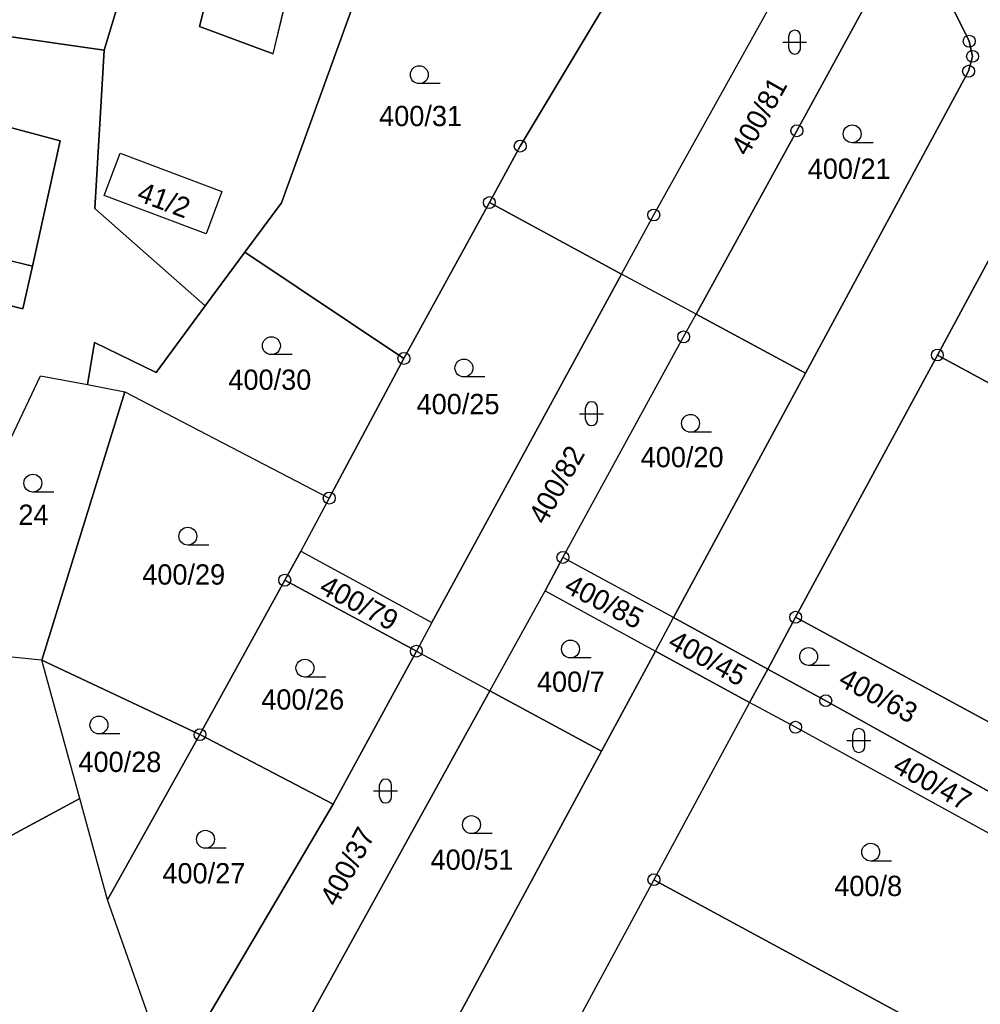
# Model space of a CAD drawing. Extents: x -654083 to -650132, y -1099819 to -1096699.
# Drawn here: x -652350.7 to -652270.1, y -1098133.4 to -1098050.9 of the extents above; entities that cross this region are included whole.
import ezdxf

# ---------------------------------------------------------------- set-up
doc = ezdxf.new("R2010")
doc.units = 0
for name, color, linetype in [('Geodetické body', 7, 'Continuous'), ('Hranice - vnitř_ kresba', 7, 'Continuous'), ('Obvody jako plochy', 7, 'Continuous'), ('Parcelní čísla', 7, 'Continuous'), ('Značky kultur', 7, 'Continuous')]:
    doc.layers.add(name, color=color, linetype=linetype)

msp = doc.modelspace()

# ---------------------------------------------------------------- linework, layer by layer
at = {"layer": 'Geodetické body'}
for centre, radius in [((-652271.05, -1098052.68), 0.5), ((-652271.05, -1098052.68), 0.001), ((-652270.77, -1098053.95), 0.5), ((-652270.77, -1098053.95), 0.001), ((-652271.1, -1098055.2), 0.5), ((-652271.1, -1098055.2), 0.001), ((-652285.49, -1098060.19), 0.5), ((-652285.49, -1098060.19), 0.001), ((-652308.69, -1098061.47), 0.5), ((-652308.69, -1098061.47), 0.001), ((-652311.28, -1098066.21), 0.5), ((-652311.28, -1098066.21), 0.001), ((-652297.49, -1098067.25), 0.5), ((-652297.49, -1098067.25), 0.001), ((-652294.99, -1098077.47), 0.5), ((-652294.99, -1098077.47), 0.001), ((-652318.44, -1098079.28), 0.5), ((-652273.72, -1098078.99), 0.5), ((-652273.72, -1098078.99), 0.001), ((-652318.44, -1098079.28), 0.001), ((-652324.7, -1098090.99), 0.5), ((-652324.7, -1098090.99), 0.001), ((-652305.11, -1098095.96), 0.5), ((-652305.11, -1098095.96), 0.001), ((-652328.43, -1098097.87), 0.5), ((-652328.43, -1098097.87), 0.001), ((-652285.6, -1098100.98), 0.5), ((-652285.6, -1098100.98), 0.001), ((-652317.4, -1098103.82), 0.5), ((-652317.4, -1098103.82), 0.001), ((-652283.08, -1098107.97), 0.5), ((-652283.08, -1098107.97), 0.001), ((-652285.61, -1098110.2), 0.5), ((-652335.54, -1098110.82), 0.5), ((-652285.61, -1098110.2), 0.001), ((-652335.54, -1098110.82), 0.001), ((-652297.48, -1098122.98), 0.5), ((-652297.48, -1098122.98), 0.001)]:
    msp.add_circle(centre, radius, dxfattribs=at)
at = {"layer": 'Hranice - vnitř_ kresba'}
for p, q in [((-652329.39, -1098053.75), (-652325.09, -1098035.62)), ((-652335.57, -1098051.46), (-652333.97, -1098044.99)), ((-652329.39, -1098053.75), (-652335.57, -1098051.46)), ((-652356.45, -1098069.89), (-652349.59, -1098071.53))]:
    msp.add_line(p, q, dxfattribs=at)
at = {"layer": 'Obvody jako plochy'}
for points in [[(-652283.6, -1098024.55), (-652287.57, -1098022.38), (-652299.65, -1098046.36), (-652308.69, -1098061.47), (-652311.28, -1098066.21), (-652300.19, -1098072.2), (-652297.49, -1098067.25), (-652279.65, -1098035.21), (-652276.24, -1098028.56)], [(-652260.84, -1098055.14), (-652273.72, -1098078.99), (-652285.6, -1098100.98), (-652287.94, -1098105.32), (-652295.85, -1098101.01), (-652284.78, -1098080.52), (-652271.1, -1098055.2), (-652270.77, -1098053.95), (-652271.05, -1098052.68), (-652275.93, -1098042.78), (-652266.76, -1098026.38), (-652268.48, -1098031.66), (-652253.8, -1098039.57)], [(-652318.27, -1098037.45), (-652320.62, -1098036.82), (-652332.1, -1098029.44), (-652333.63, -1098033.34), (-652335.08, -1098032.88), (-652338.27, -1098031.87), (-652341.44, -1098046.38), (-652343.57, -1098053.42), (-652344.35, -1098066.72), (-652335.1, -1098074.87), (-652331.77, -1098070.37), (-652328.7, -1098066.22)], [(-652329.39, -1098053.75), (-652325.09, -1098035.62), (-652333.63, -1098033.34), (-652336.58, -1098044.22), (-652333.97, -1098044.99), (-652335.57, -1098051.46)], [(-652299.65, -1098046.36), (-652319.73, -1098034.98), (-652320.62, -1098036.82), (-652318.27, -1098037.45), (-652328.7, -1098066.22), (-652331.77, -1098070.37), (-652318.44, -1098079.28), (-652311.28, -1098066.21), (-652308.69, -1098061.47)], [(-652275.93, -1098042.78), (-652278.28, -1098046.99), (-652285.49, -1098060.19), (-652293.94, -1098075.57), (-652300.19, -1098072.2), (-652297.49, -1098067.25), (-652279.65, -1098035.21)], [(-652271.1, -1098055.2), (-652284.78, -1098080.52), (-652293.94, -1098075.57), (-652285.49, -1098060.19), (-652278.28, -1098046.99), (-652275.93, -1098042.78), (-652271.05, -1098052.68), (-652270.77, -1098053.95)], [(-652348.9, -1098080.73), (-652344.98, -1098081.47), (-652344.39, -1098077.93), (-652339.22, -1098080.46), (-652335.1, -1098074.87), (-652344.35, -1098066.72), (-652343.57, -1098053.42), (-652360.95, -1098050.95), (-652364.91, -1098059.51), (-652358.22, -1098061.13), (-652357.52, -1098058.3), (-652347.27, -1098061.03), (-652349.59, -1098071.53), (-652350.38, -1098075.11), (-652357.25, -1098073.39), (-652360.8, -1098072.57), (-652375.17, -1098080.77), (-652351.38, -1098085.94)], [(-652255.63, -1098057.57), (-652241.86, -1098065.29), (-652239.31, -1098067.73), (-652234.55, -1098070.66), (-652243.62, -1098089.21), (-652246.14, -1098093.94), (-652273.72, -1098078.99), (-652260.84, -1098055.14)], [(-652349.59, -1098071.53), (-652347.27, -1098061.03), (-652357.52, -1098058.3), (-652358.22, -1098061.13), (-652364.91, -1098059.51), (-652367.09, -1098067.32), (-652375.17, -1098080.77), (-652360.8, -1098072.57), (-652357.25, -1098073.39), (-652350.38, -1098075.11)], [(-652364.91, -1098059.51), (-652358.22, -1098061.13), (-652357.52, -1098058.3), (-652347.27, -1098061.03), (-652349.59, -1098071.53), (-652356.45, -1098069.89), (-652357.25, -1098073.39), (-652360.8, -1098072.57), (-652359.97, -1098069.04), (-652367.09, -1098067.32)], [(-652343.56, -1098065.62), (-652342.24, -1098062.08), (-652333.7, -1098065.28), (-652335.02, -1098068.82)], [(-652333.7, -1098065.28), (-652335.02, -1098068.82), (-652343.56, -1098065.62), (-652342.24, -1098062.08)], [(-652333.7, -1098065.28), (-652335.02, -1098068.82), (-652343.56, -1098065.62), (-652342.24, -1098062.08)], [(-652300.19, -1098072.2), (-652311.28, -1098066.21), (-652318.44, -1098079.28), (-652324.7, -1098090.99), (-652327.08, -1098095.44), (-652316.1, -1098101.42)], [(-652324.7, -1098090.99), (-652318.44, -1098079.28), (-652331.77, -1098070.37), (-652335.1, -1098074.87), (-652339.22, -1098080.46), (-652344.39, -1098077.93), (-652344.98, -1098081.47), (-652341.84, -1098082.08)], [(-652311.23, -1098107.15), (-652306.6, -1098098.77), (-652305.11, -1098095.96), (-652294.99, -1098077.47), (-652293.94, -1098075.57), (-652300.19, -1098072.2), (-652316.1, -1098101.42), (-652317.4, -1098103.82)], [(-652284.78, -1098080.52), (-652295.85, -1098101.01), (-652305.11, -1098095.96), (-652294.99, -1098077.47), (-652293.94, -1098075.57)], [(-652273.72, -1098078.99), (-652246.14, -1098093.94), (-652251.67, -1098104.34), (-652257.9, -1098116.01), (-652285.6, -1098100.98)], [(-652341.84, -1098082.08), (-652348.8, -1098104.58), (-652367.35, -1098102.73), (-652366.91, -1098097.18), (-652363.31, -1098098.3), (-652362.49, -1098095.54), (-652355.47, -1098097.67), (-652353.47, -1098090.56), (-652372.41, -1098084.66), (-652374.63, -1098091.76), (-652376.21, -1098096.84), (-652379.95, -1098094.79), (-652375.17, -1098080.77), (-652351.38, -1098085.94), (-652348.9, -1098080.73), (-652344.98, -1098081.47)], [(-652327.08, -1098095.44), (-652328.43, -1098097.87), (-652335.54, -1098110.82), (-652348.8, -1098104.58), (-652341.84, -1098082.08), (-652324.7, -1098090.99)], [(-652316.1, -1098101.42), (-652317.4, -1098103.82), (-652328.43, -1098097.87), (-652327.08, -1098095.44)], [(-652295.85, -1098101.01), (-652305.11, -1098095.96), (-652306.6, -1098098.77), (-652297.36, -1098103.81)], [(-652317.4, -1098103.82), (-652324.37, -1098116.66), (-652335.54, -1098110.82), (-652328.43, -1098097.87)], [(-652306.6, -1098098.77), (-652297.36, -1098103.81), (-652301.89, -1098112.2), (-652311.23, -1098107.15)], [(-652287.94, -1098105.32), (-652289.46, -1098108.13), (-652297.36, -1098103.81), (-652295.85, -1098101.01)], [(-652285.6, -1098100.98), (-652257.9, -1098116.01), (-652260.36, -1098120.62), (-652283.08, -1098107.97), (-652287.94, -1098105.32)], [(-652348.8, -1098104.58), (-652367.35, -1098102.73), (-652376.94, -1098102.1), (-652375.09, -1098108.69), (-652379.86, -1098116.48), (-652371.41, -1098121.18), (-652362.11, -1098126.39), (-652357.82, -1098117.99), (-652353.4, -1098120.37), (-652345.62, -1098116.16)], [(-652311.23, -1098107.15), (-652326.55, -1098134.91), (-652330.03, -1098136.21), (-652333.75, -1098138.69), (-652336.77, -1098143.18), (-652337.98, -1098139.73), (-652324.37, -1098116.66), (-652317.4, -1098103.82)], [(-652289.46, -1098108.13), (-652297.48, -1098122.98), (-652308.89, -1098144.1), (-652276.57, -1098161.63), (-652277.81, -1098164.27), (-652287.06, -1098159.19), (-652306.84, -1098148.4), (-652327.75, -1098137.08), (-652326.55, -1098134.91), (-652326.07, -1098134.73), (-652313.79, -1098134.25), (-652301.89, -1098112.2), (-652297.36, -1098103.81)], [(-652335.54, -1098110.82), (-652343.28, -1098124.66), (-652345.62, -1098116.16), (-652348.8, -1098104.58)], [(-652257.7, -1098121.96), (-652257.51, -1098122.07), (-652258.96, -1098124.77), (-652265.36, -1098121.32), (-652285.61, -1098110.2), (-652289.46, -1098108.13), (-652287.94, -1098105.32), (-652283.08, -1098107.97), (-652260.36, -1098120.62)], [(-652311.23, -1098107.15), (-652301.89, -1098112.2), (-652313.79, -1098134.25), (-652326.07, -1098134.73), (-652326.55, -1098134.91)], [(-652266.33, -1098139.88), (-652261.08, -1098128.71), (-652258.96, -1098124.77), (-652265.36, -1098121.32), (-652285.61, -1098110.2), (-652289.46, -1098108.13), (-652297.48, -1098122.98)], [(-652324.37, -1098116.66), (-652337.98, -1098139.73), (-652343.28, -1098124.66), (-652335.54, -1098110.82)], [(-652343.28, -1098124.66), (-652345.62, -1098116.16), (-652353.4, -1098120.37), (-652357.82, -1098117.99), (-652362.11, -1098126.39), (-652371.41, -1098121.18), (-652370.69, -1098134.78), (-652355.32, -1098140.03), (-652347.23, -1098147.65), (-652342.01, -1098148.1), (-652336.77, -1098143.18), (-652337.98, -1098139.73)], [(-652266.33, -1098139.88), (-652297.48, -1098122.98), (-652308.89, -1098144.1), (-652276.57, -1098161.63), (-652268.44, -1098144.36)]]:
    msp.add_lwpolyline(points, close=True, dxfattribs=at)
msp.add_lwpolyline([(-652360.95, -1098050.95), (-652343.57, -1098053.42), (-652341.44, -1098046.38)], dxfattribs=at)
at = {"layer": 'Značky kultur'}
for p, q in [((-652286.68, -1098052.76), (-652284.68, -1098052.76)), ((-652286.18, -1098053.26), (-652286.18, -1098052.26)), ((-652285.18, -1098053.26), (-652285.18, -1098052.26)), ((-652315.4, -1098056.24), (-652317.15, -1098056.24)), ((-652279.11, -1098061.2), (-652280.86, -1098061.2)), ((-652327.8, -1098078.96), (-652329.55, -1098078.96)), ((-652311.66, -1098080.83), (-652313.41, -1098080.83)), ((-652303.71, -1098083.91), (-652301.71, -1098083.91)), ((-652303.21, -1098084.41), (-652303.21, -1098083.41)), ((-652302.21, -1098084.41), (-652302.21, -1098083.41)), ((-652292.66, -1098085.47), (-652294.41, -1098085.47)), ((-652347.8, -1098090.48), (-652349.55, -1098090.48)), ((-652334.81, -1098094.93), (-652336.56, -1098094.93)), ((-652302.73, -1098104.39), (-652304.48, -1098104.39)), ((-652282.76, -1098105.02), (-652284.51, -1098105.02)), ((-652324.99, -1098105.99), (-652326.74, -1098105.99)), ((-652342.26, -1098110.76), (-652344.01, -1098110.76)), ((-652281.3, -1098111.31), (-652279.3, -1098111.31)), ((-652280.8, -1098111.81), (-652280.8, -1098110.81)), ((-652279.8, -1098111.81), (-652279.8, -1098110.81)), ((-652320.98, -1098115.54), (-652318.98, -1098115.54)), ((-652320.48, -1098116.04), (-652320.48, -1098115.04)), ((-652319.48, -1098116.04), (-652319.48, -1098115.04)), ((-652311.03, -1098119.11), (-652312.78, -1098119.11)), ((-652333.33, -1098120.34), (-652335.08, -1098120.34)), ((-652277.56, -1098121.42), (-652279.31, -1098121.42))]:
    msp.add_line(p, q, dxfattribs=at)
for centre in [(-652317.15, -1098055.49), (-652280.86, -1098060.45), (-652329.55, -1098078.21), (-652313.41, -1098080.08), (-652294.41, -1098084.72), (-652349.55, -1098089.73), (-652336.56, -1098094.18), (-652304.48, -1098103.64), (-652284.51, -1098104.27), (-652326.74, -1098105.24), (-652344.01, -1098110.01), (-652312.78, -1098118.36), (-652335.08, -1098119.59), (-652279.31, -1098120.67)]:
    msp.add_circle(centre, 0.75, dxfattribs=at)
for centre, start, end in [((-652285.68, -1098052.26), 0, 180), ((-652285.68, -1098053.26), 180, 0), ((-652302.71, -1098083.41), 0, 180), ((-652302.71, -1098084.41), 180, 0), ((-652280.3, -1098110.81), 0, 180), ((-652280.3, -1098111.81), 180, 0), ((-652319.98, -1098115.04), 0, 180), ((-652319.98, -1098116.04), 180, 0)]:
    msp.add_arc(centre, 0.5, start, end, dxfattribs=at)

# ---------------------------------------------------------------- texts
at = {"layer": 'Parcelní čísla'}
for s, rotation, p in [('400/81', 60.651, (-652289.647, -1098062.405)), ('41/2', 339.624, (-652340.92, -1098066.02)), ('400/82', 60.795, (-652306.601, -1098093.304)), ('400/79', 331.722, (-652325.654, -1098098.871)), ('400/85', 332.46, (-652305.115, -1098098.806)), ('400/45', 331.191, (-652296.42, -1098103.47)), ('400/63', 331.731, (-652282.13, -1098106.63)), ('400/47', 330.822, (-652277.57, -1098113.87)), ('400/37', 61.848, (-652324.078, -1098125.325))]:
    msp.add_text(s, height=1.7, rotation=rotation, dxfattribs=at).set_placement(p)
for s, p in [('400/31', (-652320.52, -1098059.8)), ('400/21', (-652284.59, -1098064.22)), ('400/30', (-652333.16, -1098081.91)), ('400/25', (-652317.38, -1098083.95)), ('400/20', (-652298.593, -1098088.4)), ('24', (-652350.76, -1098093.23)), ('400/29', (-652340.38, -1098098.24)), ('400/7', (-652307.291, -1098107.23)), ('400/26', (-652330.4, -1098108.72)), ('400/28', (-652345.73, -1098113.95)), ('400/51', (-652316.209, -1098122.15)), ('400/27', (-652338.69, -1098123.29)), ('400/8', (-652282.364, -1098124.35))]:
    msp.add_text(s, height=1.7, dxfattribs=at).set_placement(p)

doc.saveas('drawing.dxf')
